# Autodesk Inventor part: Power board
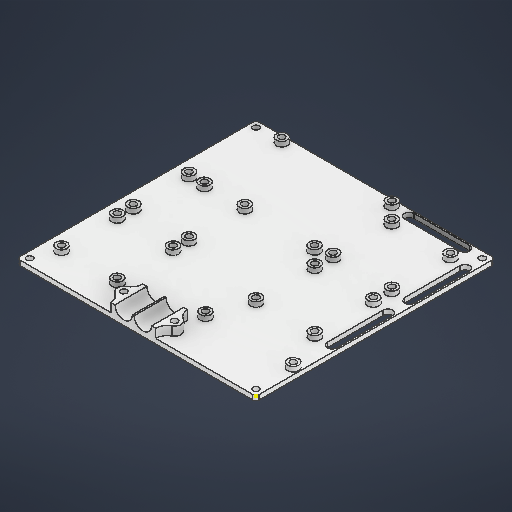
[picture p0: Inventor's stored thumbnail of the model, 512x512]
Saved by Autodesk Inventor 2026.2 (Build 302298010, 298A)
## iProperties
Created: 2026-04
Part Number: Power board
Material: ABS 플라스틱
Document SubType Name: Modeling
Designer: work
Density: 1.06 g/cm^3
Appearance: 매끄러움 - 흰색
Author: work
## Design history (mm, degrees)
sketch "스케치1"
  geometry: L1 (0, -150)-(150, -150); L2 (150, -150)-(150, 0); L3 (150, 0)-(0, 0); L4 (0, 0)-(0, -150); L5 (0, -150)-(150, 0); L6 (150, -150)-(0, 0); L7 (4, -4)-(146, -4); L8 (146, -4)-(146, -146); L9 (146, -146)-(4, -146); L10 (4, -146)-(4, -4); L11 (4, -4)-(146, -146); L12 (146, -4)-(4, -146); L13 (50.8, -99.2)-(50.8, -136); L14 (14, -99.2)-(50.8, -99.2); L15 (50.8, -136)-(14, -136); L16 (14, -136)-(14, -99.2); L17 (14, -99.2)-(50.8, -136); L18 (50.8, -99.2)-(14, -136); L19 (32.4, -117.6)-(32.4, -146); L20 (49.9, -143)-(14.9, -143); L21 (14.9, -146)-(49.9, -146); L22 (14.9, -149)-(49.9, -149); L23 (32.4, -69.232)-(4, -69.232); L24 (14, -87.632)-(14, -50.832); L25 (14, -50.832)-(50.8, -50.832); L26 (50.8, -87.632)-(14, -87.632); L27 (50.8, -50.832)-(14, -87.632); L28 (50.8, -50.832)-(50.8, -87.632); L29 (50.8, -87.632)-(14, -50.832); L30 (4, -86.732)-(4, -51.732); L31 (7, -86.732)-(7, -51.732); L32 (1, -51.732)-(1, -86.732); L33 (60.8, -146)-(60.8, -97.5); L34 (60.8, -97.5)-(129.8, -97.5); L35 (129.8, -146)-(60.8, -146); L36 (129.8, -97.5)-(60.8, -146); L37 (129.8, -97.5)-(129.8, -146); L38 (60.8, -97.5)-(129.8, -146); L39 (8.5, -13.832)-(54.5, -13.832); L40 (54.5, -13.832)-(8.5, -40.832); L41 (54.5, -13.832)-(54.5, -40.832); L42 (59, -27.332)-(4, -27.332); L43 (8.5, -13.832)-(54.5, -40.832); L44 (8.5, -40.832)-(8.5, -13.832); L45 (54.5, -40.832)-(8.5, -40.832); L46 (4, -135.1)-(4, -100.1); L47 (7, -135.1)-(7, -100.1); L48 (1, -100.1)-(1, -135.1); L49 (105, -18)-(140, -18); L50 (140, -18)-(140, -53); L51 (140, -53)-(105, -53); L52 (105, -53)-(105, -18); L53 (105, -18)-(140, -53); L54 (140, -18)-(105, -53); L55 (105, -35.5)-(140, -35.5); L56 (122.5, -53)-(122.5, -18); L57 (140, -98)-(105, -98); L58 (105, -80.5)-(140, -80.5); L59 (105, -63)-(140, -98); L60 (140, -63)-(140, -98); L61 (122.5, -98)-(122.5, -63); L62 (105, -98)-(105, -63); L63 (105, -63)-(140, -63); L64 (140, -63)-(105, -98); C1 r 2 at (50.8, -99.2); C2 r 2 at (14, -99.2); C3 r 2 at (14, -136); C4 r 2 at (50.8, -136); C5 r 2 at (14, -50.832); C6 r 2 at (14, -87.632); C7 r 2 at (50.8, -50.832); C8 r 2 at (50.8, -87.632); C9 r 2 at (60.8, -97.5); C10 r 2 at (129.8, -97.5); C11 r 2 at (60.8, -146); C12 r 2 at (129.8, -146); C13 r 2 at (59, -27.332); C14 r 2 at (4, -27.332); C15 r 2 at (4, -4); C16 r 2 at (4, -146); C17 r 2 at (146, -146); C18 r 2 at (146, -4); C19 r 2 at (140, -18); C20 r 2 at (140, -53); C21 r 2 at (105, -53); C22 r 2 at (105, -18); C23 r 2 at (140, -98); C24 r 2 at (105, -63); C25 r 2 at (140, -63); C26 r 2 at (105, -98); A1 r 3 centre (49.9, -146) between (49.9, -149) and (49.9, -143); A2 r 3 centre (14.9, -146) between (14.9, -143) and (14.9, -149); A3 r 3 centre (4, -51.732) between (7, -51.732) and (1, -51.732); A4 r 3 centre (4, -86.732) between (1, -86.732) and (7, -86.732); A5 r 3 centre (4, -135.1) between (1, -135.1) and (7, -135.1); A6 r 3 centre (4, -100.1) between (7, -100.1) and (1, -100.1); 8 further points
  constraints: 134 end point, 32 centre point, 29 midpoint, 27 coincident, 19 parallel, 12 point on circle, 12 tangent, 10 horizontal, 8 perpendicular, 7 point on line, 2 vertical, 1 collinear
  dimensions: "d0" = 150 distance of L3.end L2.end; "d1" = 150 distance of L2.end L1.end; "d2" = 4 distance between parallel lines of L2 L8; "d3" = 36.8 distance of L13.end L15.end; "d4" = 36.8 distance of L13.start L13.end; "d5" = 4 diameter of C2; "d6" = 4 diameter of C3; "d7" = 4 diameter of C4; "d8" = 4 diameter of C1; "d9" = 6 diameter of A1; "d10" = 35 distance of L21.start L21.end; "d11" = 10 horizontal distance of L9.end C3.centre; "d12" = 10 horizontal distance of L9.end L15.end; "d13" = 36.8 distance of L24.start L24.end; "d14" = 36.8 distance of L26.start L24.start; "d15" = 4 diameter of C7; "d16" = 4 diameter of C5; "d17" = 4 diameter of C6; "d18" = 4 diameter of C8; "d19" = 6 diameter of A3; "d20" = 35 distance of L30.start L30.end; "d21" = 28.4 distance of L23.start L23.end; "d22" = 69 distance of L35.start L33.start; "d23" = 48.5 distance of L34.end L35.start; "d24" = 4 diameter of C9; "d25" = 4 diameter of C11; "d26" = 4 diameter of C12; "d27" = 4 diameter of C10; "d28" = 10 distance between parallel lines of L13 L33; "d29" = 11.56791 distance between parallel lines of L14 L26; "d30" = 55 distance of L42.start L42.end; "d31" = 46 distance of L41.end L40.end; "d32" = 27 distance of L39.end L41.end; "d33" = 4 diameter of C13; "d34" = 4 diameter of C14; "d35" = 10 distance between parallel lines of L25 L45; "d36" = 4 diameter of C15; "d37" = 4 diameter of C16; "d38" = 4 diameter of C17; "d39" = 4 diameter of C18; "d40" = 17.5 distance of point (4, -117.6) L46.end; "d41" = 6 diameter of A6; "d48" = 35 distance of L50.end L51.end; "d49" = 35 distance of L49.end L50.end; "d50" = 14 distance between parallel lines of L7 L49; "d51" = 6 distance between parallel lines of L8 L50; "d52" = 4 diameter of C19; "d53" = 4 diameter of C20; "d54" = 4 diameter of C21; "d55" = 4 diameter of C22; "d56" = 35 distance of L57.start L57.end; "d57" = 35 distance of L60.start L57.start; "d58" = 4 diameter of C25; "d59" = 4 diameter of C23; "d60" = 4 diameter of C26; "d61" = 4 diameter of C24; "d62" = 10 distance between parallel lines of L63 L51
extrude "돌출1" new body sketch "스케치1" distance "d42" = 3; taper "d43" = 0 deg
sketch "스케치2"
  geometry: L1 (-7, 100.1)-(-7, 135.1) reference; L2 (-150, 150)-(-150, 0) reference; L3 (-150, 0)-(0, 0) reference; L4 (0, 0)-(0, 150) reference; L5 (0, 150)-(-150, 150) reference; L6 (-1, 135.1)-(-1, 100.1) reference; L7 (-7, 100.1)-(-7, 135.1) reference; L8 (-7, 51.732)-(-7, 86.732) reference; L9 (-1, 86.732)-(-1, 51.732) reference; L10 (-49.9, 149)-(-14.9, 149) reference; L11 (-14.9, 143)-(-49.9, 143) reference; C1 r 2 at (-146, 4) reference; C2 r 2 at (-4, 146) reference; C3 r 2 at (-4, 27.332) reference; C4 r 2 at (-129.8, 146) reference; C5 r 2 at (-129.8, 97.5) reference; C6 r 2 at (-50.8, 87.632) reference; C7 r 2 at (-50.8, 50.832) reference; C8 r 2 at (-14, 87.632) reference; C9 r 2 at (-14, 50.832) reference; C10 r 2 at (-50.8, 136) reference; C11 r 2 at (-14, 136) reference; C12 r 2 at (-14, 99.2) reference; C13 r 2 at (-50.8, 99.2) reference; C14 r 2 at (-60.8, 97.5) reference; C15 r 2 at (-60.8, 146) reference; C16 r 2 at (-59, 27.332) reference; C17 r 2 at (-4, 4) reference; C18 r 2 at (-146, 146) reference; C19 r 2 at (-14, 87.632) reference; C20 r 2 at (-14, 50.832) reference; C21 r 2 at (-129.8, 146) reference; C22 r 3.5 at (-4, 27.332); C23 r 2 at (-105, 18) reference; C24 r 2 at (-140, 18) reference; C25 r 2 at (-140, 53) reference; C26 r 2 at (-105, 53) reference; C27 r 2 at (-105, 63) reference; C28 r 2 at (-140, 63) reference; C29 r 2 at (-140, 98) reference; C30 r 2 at (-105, 98) reference; A1 r 3 centre (-4, 135.1) between (-1, 135.1) and (-7, 135.1) reference; A2 r 3 centre (-4, 100.1) between (-7, 100.1) and (-1, 100.1) reference; A3 r 3 centre (-4, 86.732) between (-1, 86.732) and (-7, 86.732) reference; A4 r 3 centre (-4, 51.732) between (-7, 51.732) and (-1, 51.732) reference; A5 r 3 centre (-14.9, 146) between (-14.9, 143) and (-14.9, 149) reference; A6 r 3 centre (-49.9, 146) between (-49.9, 149) and (-49.9, 143) reference; 23 further points
  constraints: 23 coincident, 1 centre point
  dimensions: "d44" = 7 diameter of C22
  node "투영된 루프1"
extrude "돌출2" join sketch "스케치2" distance "d45" = 3; taper "d46" = 0 deg
fillet "모깎기1" dims "d47" = 2
sketch "스케치3"
  geometry: 1 further point
sketch "스케치4"
  geometry: L1 (146, 3)-(146, 0) reference; L2 (0, 3)-(146, 3) reference; L3 (0, 0)-(0, 3) reference; L4 (0, 0)-(146, 0) reference; L5 (0, 3)-(146, 3) reference; L6 (146, 3)-(0, 3) reference; L7 (57, 3)-(57, 8.5); L8 (57, 8.5)-(85, 8.5); L9 (85, 8.5)-(85, 3); L10 (41, 6)-(45, 6) reference; L11 (41, 0)-(45, 0) reference; C1 r 5.5 at (65, 8.5); C2 r 5.5 at (77, 8.5); 10 further points
  constraints: 6 end point, 3 perpendicular, 2 centre point, 2 point on line, 2 tangent, 1 midpoint
  dimensions: "d63" = 11 diameter of C1; "d64" = 11 diameter of C2; "d65" = 12 distance of C2.centre C1.centre; "d66" = 8 distance from line of L9 C2.centre; "d67" = 8 distance of L7.end C1.centre; "d68" = 28 distance of L7.end L8.end; "d69" = 14 distance from line of point (43, 6) L7
extrude "돌출3" join sketch "스케치4" distance "d70" = 20; taper "d71" = 0 deg
sketch "스케치5" dims "d76" = 8
  geometry: L1 (0, 0)-(0, 20) reference; L2 (0, 10)-(28, 10); L3 (28, 20)-(28, 0) reference; L4 (-2, 10)-(30, 10); L5 (25.5, 20)-(28, 20) reference; L6 (28, 0)-(28, 20) reference; L7 (-57, 0)-(89, 0) reference; L8 (14, 0)-(14, 20); L9 (14.5, 0)-(14.5, 20) reference; L10 (13.5, 20)-(14.5, 20) reference; C1 r 2 at (-2, 10); C2 r 2 at (30, 10); C3 r 4 at (-2, 10); A1 r 7.333 centre (35.333, 20) between (28, 20) and (31.882, 13.529); A2 r 7.333 centre (35.333, 0) between (31.882, 6.471) and (28, 0); A3 r 7.333 centre (-7.333, 0) between (0, 0) and (-3.882, 6.471); A4 r 7.333 centre (-7.333, 20) between (-3.882, 13.529) and (0, 20); 8 further points
  constraints: 8 point on circle, 7 centre point, 6 end point, 6 symmetric about line, 5 midpoint, 2 coincident, 1 collinear, 1 parallel, 1 point on line, 1 tangent, 7 other
  dimensions: "d72" = 4 diameter of C1; "d73" = 4 diameter of C2; "d74" = 32 distance of L4.end L4.start; "d75" = 8 diameter of C3
extrude "돌출4" join sketch "스케치5" stored distance "d77" = 0; taper "d78" = 0 deg
node "솔리드1"
feature "스케치 연계 패턴1"
node "투영된 루프2"
node "투영된 루프3"
